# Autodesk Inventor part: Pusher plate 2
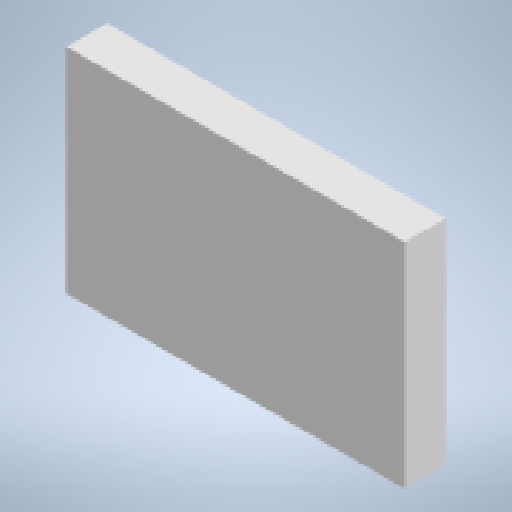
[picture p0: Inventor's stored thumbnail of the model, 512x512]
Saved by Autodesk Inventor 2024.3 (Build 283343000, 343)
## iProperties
Created: 2024-12
Part Number: Pusher plate 2
Material: Generic
Document SubType Name: Modeling
Designer: ruhr
Density: 1 g/cm^3
Appearance: Default
Author: ruhr
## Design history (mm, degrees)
sketch "Sketch1"
  geometry: L1 (20.743, 13.101)-(20.743, -13.101); L2 (20.743, -13.101)-(-20.743, -13.101); L3 (-20.743, -13.101)-(-20.743, 13.101); L4 (-20.743, 13.101)-(20.743, 13.101); L5 (20.743, 13.101)-(-20.743, -13.101); L6 (20.743, -13.101)-(-20.743, 13.101); 1 further point
  constraints: 12 end point, 2 midpoint, 2 parallel, 1 perpendicular, 1 vertical
extrude "Extrusion1" new body sketch "Sketch1" distance "d0" = 5; taper "d1" = 0 deg
body "Solid1"
